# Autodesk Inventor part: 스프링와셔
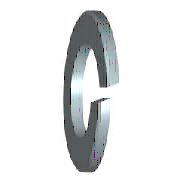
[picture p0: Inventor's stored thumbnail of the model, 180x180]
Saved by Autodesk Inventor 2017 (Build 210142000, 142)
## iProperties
Created: 2012-02
Part Number: 스프링와셔
Material: 강철, 연강
Description: 스프링 와셔
Document SubType Name: Modeling
Standard: JIS B 1251
Designer: mduedu
Standards Organization: JIS
Language: ko-KR
Size Designation: 번호 2 4
Categories: <MemberInstance><Categories><Category DisplayName="조임쇠" InternalName="e4da775c-781d-43d5-af7c-5136215cf5a6" Mnemonic="FSTN"><Category DisplayName="와셔" InternalN
Density: 1 g/cm^3
Appearance: 파란색 - 벽 페인트 - 광택
IsCustomPart: 1
Author: mduedu
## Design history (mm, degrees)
sketch "스케치1"
  geometry: C1 r 3.8 at (0, 0); C2 r 2.05 at (0, 0); 1 further point
  constraints: 2 centre point, 2 coincident
  dimensions: "d0" = 4.1 diameter of C2 (= SD1); "d1" = 7.6 diameter of C1 (= SD2)
extrude "본체" new body sketch "스케치1" distance "d2" = 1 (= SD); taper "d3" = 0 deg
sketch "스케치2"
  geometry: L1 (0, -2.05)-(0, 2.05) reference; L2 (1, 3.8)-(1, -3.8) reference; L3 (-1.2, 0)-(7.2, 0) reference; L4 (0, -0.2)-(1, 0.164); L5 (0, 0.2)-(1, 0.564)
  constraints: 4 end point, 4 point on line, 1 parallel
  dimensions: "d4" = 0.2 distance from line of L3 L4.start (= 0.2 x SD); "d5" = 0.2 distance from line of L3 L5.start (= 0.2 x SD); "d6" = 70 deg angle of L2 L4 (= FAWI)
extrude "절단부" cut sketch "스케치2" stored distance "d7" = 1 (= SD); taper "d8" = 0 deg
workaxis "Work Axis1"
workplane "Work Plane1"
body "Solid1"
other parameters: "SD1" = 4.1 [user parameter; used in 1 equation term], "SD2" = 7.6 [user parameter; used in 1 equation term], "SD" = 1 [user parameter; used in 4 equation terms], "FAWI" = 70 deg [user parameter; used in 1 equation term], "d9" = 0, "d10" = 0, "d11" = 0, "d12" = 0, "SDI" = 1.4 [user parameter], "NND" = 4 [user parameter]
